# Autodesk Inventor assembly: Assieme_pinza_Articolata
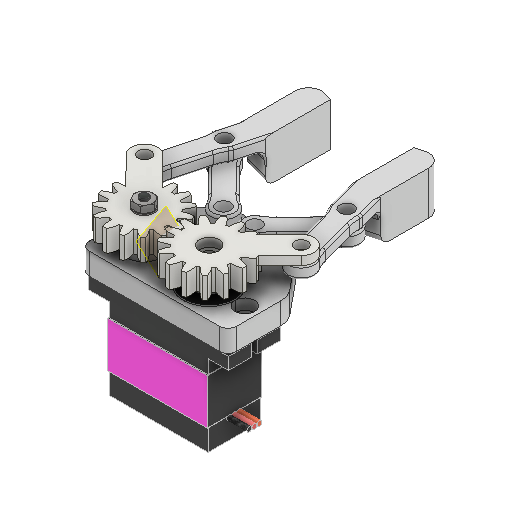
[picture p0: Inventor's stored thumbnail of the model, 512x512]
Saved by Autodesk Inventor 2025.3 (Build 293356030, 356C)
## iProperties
Created: 2026-03
Part Number: Assieme_pinza_Articolata
Document SubType Name: Assembly
Designer: R5800u
Author: R5800u
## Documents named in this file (11)
- C:\Users\R5800u\Desktop\robot mg90s\Assieme_pinza_Articolata.iam
- C:\Users\R5800u\Desktop\robot mg90s\MG90_ldb.ipt
- C:\Users\R5800u\Desktop\robot mg90s\Assieme_ingranaggi_mg90s.iam
- C:\Users\R5800u\Desktop\robot mg90s\MG90S ARM.ipt
- C:\Users\R5800u\Desktop\robot mg90s\blocco_pinza_articolata.ipt
- C:\Users\R5800u\Desktop\robot mg90s\leva1.ipt
- C:\Users\R5800u\Desktop\robot mg90s\leva2.ipt
- C:\Users\R5800u\Desktop\robot mg90s\leva2b.ipt
- C:\Users\R5800u\Documents\Inventor\Content Center Files\R2025\it-IT\ISO 14580_2011(E)\ISO 14580 M2x12-4.8.ipt
- C:\Users\R5800u\Documents\Inventor\Content Center Files\R2025\it-IT\AS 1112 (2)\AS 1112 - M2  Tipo 5.ipt
- C:\Users\R5800u\Documents\Inventor\Content Center Files\R2025\it-IT\AS 1237 (2.1)\AS 1237 - 2.ipt
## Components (11 placed, 10 different names)
1. MG90_ldb:1 — Coincidente:1, Rotazionale:1, Angolo:1, Allineato:1
2. Assieme_ingranaggi_mg90s:1 [sub-assembly] — Coincidente:1, Coincidente:2, Angolo:1, Allineato:2, Angolo:2, Coincidente:5, Coincidente:6, Coincidente:7, Coincidente:11
3. MG90S ARM:1 — Rotazionale:1, Coincidente:2
4. blocco_pinza_articolata:1 — Allineato:1, Rotazionale:2, Rotazionale:3, Angolo:2, Coincidente:5, Rotazionale:6, Coincidente:9
5. leva1:1 — Rotazionale:2, Rotazionale:4, Simmetria:1
6. leva1:2 — Rotazionale:3, Rotazionale:5, Simmetria:1
7. leva2:1 — Rotazionale:4, Simmetria:2, Coincidente:6
8. leva2b:1 — Rotazionale:5, Simmetria:2, Coincidente:7
9. Vite ISO 14580:2011(E) M2x12-4.8:1 — Rotazionale:6
10. AS 1112 (2) - Metrico M2  Tipo 5:1 — Coincidente:9
11. AS 1237 (2.1) 2:1 — Coincidente:11
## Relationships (19: Mate 7, RevoluteJoint 6, Angle 2, Flush 2, Symmetry 2)
- Coincidente:1 [Mate]: MG90_ldb:1 ↔ Assieme_ingranaggi_mg90s:1
- Rotazionale:1 [RevoluteJoint]: MG90_ldb:1 ↔ MG90S ARM:1
- Coincidente:2 [Mate]: Assieme_ingranaggi_mg90s:1 ↔ MG90S ARM:1
- Angolo:1 [Angle]: MG90_ldb:1 ↔ Assieme_ingranaggi_mg90s:1
- Allineato:1 [Flush]: MG90_ldb:1 ↔ blocco_pinza_articolata:1
- Rotazionale:2 [RevoluteJoint]: blocco_pinza_articolata:1 ↔ leva1:1
- Rotazionale:3 [RevoluteJoint]: blocco_pinza_articolata:1 ↔ leva1:2
- Rotazionale:4 [RevoluteJoint]: leva1:1 ↔ leva2:1
- Rotazionale:5 [RevoluteJoint]: leva1:2 ↔ leva2b:1
- Allineato:2 [Flush]: Assieme_ingranaggi_mg90s:1
- Simmetria:1 [Symmetry]: leva1:1 ↔ leva1:2
- Simmetria:2 [Symmetry]: leva2:1 ↔ leva2b:1
- Angolo:2 [Angle]: Assieme_ingranaggi_mg90s:1 ↔ blocco_pinza_articolata:1
- Coincidente:5 [Mate]: Assieme_ingranaggi_mg90s:1 ↔ blocco_pinza_articolata:1
- Coincidente:6 [Mate]: Assieme_ingranaggi_mg90s:1 ↔ leva2:1
- Coincidente:7 [Mate]: Assieme_ingranaggi_mg90s:1 ↔ leva2b:1
- Rotazionale:6 [RevoluteJoint]: blocco_pinza_articolata:1 ↔ Vite ISO 14580:2011(E) M2x12-4.8:1
- Coincidente:9 [Mate]: blocco_pinza_articolata:1 ↔ AS 1112 (2) - Metrico M2  Tipo 5:1
- Coincidente:11 [Mate]: Assieme_ingranaggi_mg90s:1 ↔ AS 1237 (2.1) 2:1
